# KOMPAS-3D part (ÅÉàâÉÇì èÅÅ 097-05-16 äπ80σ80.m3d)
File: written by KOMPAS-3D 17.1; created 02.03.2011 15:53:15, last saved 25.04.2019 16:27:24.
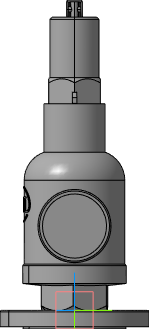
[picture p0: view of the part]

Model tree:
1. Плоскость XY
2. Плоскость ZX
3. Плоскость ZY
4. Ось X
5. Ось Y
6. Ось Z
7. Начало координат
8. Операция без истории:2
